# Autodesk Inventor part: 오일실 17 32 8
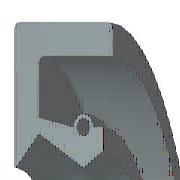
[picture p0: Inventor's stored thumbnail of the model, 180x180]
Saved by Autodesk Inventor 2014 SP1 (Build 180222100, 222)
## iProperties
IsCustomPart: 1
Created: 2012-02
Part Number: 오일실 17 32 8
Material: 고무
Description: 오일-실
Document SubType Name: Modeling
Standard: KS B 2804
Designer: mduedu
Standards Organization: KS
Language: ko-KR
Size Designation: D - 17 32 8
Categories: <MemberInstance><Categories><Category DisplayName="샤프트 부품" InternalName="7f7aeb1f-a693-4053-b835-cee3144e0d98" Mnemonic="SHFT"><Category DisplayName="실링" Intern
Density: 0.93 g/cm^3
Appearance: 고무 - 검은색 - 버전 1.1
Author: mduedu
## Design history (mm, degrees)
revolve "본체" stored, may be unused: angle "d17" = 90 deg
revolve "스프링1" stored, may be unused: angle "d18" = 90 deg
body "Solid1"
sketch "스케치1"
  geometry: L1 (0, 16)-(8, 16); L2 (8, 14.25)-(1.75, 14.25); L3 (1.75, 10.25)-(4.9, 8.5); L4 (4.9, 8.5)-(0, 8.5); L5 (0, 0)-(9.586, 0) reference; L6 (4.9, 8.5)-(6.3, 9.375); L7 (0, 18)-(0, -3) reference; L8 (-1.941, 0)-(11.507, 0) reference; L9 (4.2, 10.6)-(1.75, 11.21); L10 (1.75, 11.21)-(1.75, 14.25); L11 (0, 16)-(0, 8.588); L12 (4.9, 8.5)-(0, 8.5); L13 (1.75, 10.25)-(0.152, 8.528); L14 (8, 16)-(8, 14.25); L15 (5.6, 10.6)-(6.3, 10.6); L16 (6.3, 10.6)-(6.3, 9.375); C1 r 0.455 at (4.9, 10.6); A1 r 0.7 centre (4.9, 10.6) between (5.6, 10.6) and (4.2, 10.6); A2 r 0.088 centre (0.088, 8.588) between (0, 8.588) and (0.152, 8.528); 1 further point
  constraints: 28 end point, 5 horizontal alignment, 5 point on line, 4 point on circle, 4 vertical alignment, 3 centre point, 3 tangent, 2 collinear, 2 horizontal, 2 perpendicular, 1 coincident, 1 parallel
  dimensions: "d0" = 32 diameter of L1 L5 (= SD2); "d1" = 1.75 distance of L1.end L2.start (= SD); "d2" = 0.91 diameter of C1 (= SPDI); "d3" = 1.4 diameter of A1 (= SPDA); "d4" = 17 diameter of L3.end L5 (= NND); "d5" = 20.5 diameter of L3.start L5 (= TKDM); "d7" = 22.42 diameter of L9.end L5 (= TKDM + 0.24 x SWDT); "d8" = 1.75 distance between parallel lines of L11 L10 (= SD); "d9" = 4.9 distance from line of L11 C1.centre (= SPDST); "d10" = 21.2 diameter of C1.centre L5 (= HLDM); "d11" = 0.0875 radius of A2 (= 0.25 x LAB); "d12" = 6.3 distance between parallel lines of L11 L16 (= SDI); "d13" = 18.75 diameter of L6.end L5 (= ABDM); "d14" = 8 distance from line of L11 L1.end (= SWDT)
fillet "모깎기1" dims "d6" = 0.3 (= RR)
other parameters: "SD2" = 32 [user parameter; used in 1 equation term], "SWDT" = 8 [user parameter; used in 2 equation terms], "RR" = 0.3 [user parameter; used in 1 equation term], "SD" = 1.75 [user parameter; used in 2 equation terms], "NND" = 17 [user parameter; used in 1 equation term], "SPDA" = 1.4 [user parameter; used in 1 equation term], "SPDI" = 0.91 [user parameter; used in 1 equation term], "TKDM" = 20.5 [user parameter; used in 2 equation terms], "HLDM" = 21.2 [user parameter; used in 1 equation term], "ABDM" = 18.75 [user parameter; used in 1 equation term], "SDI" = 6.3 [user parameter; used in 1 equation term], "SPDST" = 4.9 [user parameter; used in 1 equation term], "LAB" = 0.35 [user parameter; used in 1 equation term], "d15" = 0, "d16" = 0, "d19" = 0
